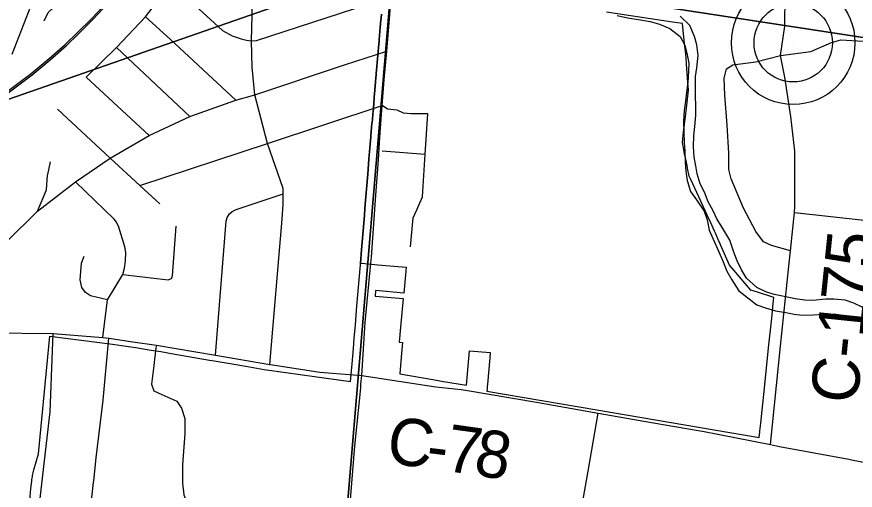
# Model space of a CAD drawing. Extents: x 0 to 34, y 0 to 22.
# Drawn here: x 7.262 to 8.273, y 14.564 to 15.134 of the extents above; entities that cross this region are included whole.
import ezdxf

# ---------------------------------------------------------------- set-up
doc = ezdxf.new("R2010")
doc.units = 0
for name, color, linetype in [('GM_X_City_Street', 7, 'Continuous'), ('GM_X_County_Road', 7, 'Continuous'), ('GM_X_County_Road_Text', 7, 'Continuous'), ('GM_X_Interchange_Ramps', 7, 'Continuous'), ('GM_X_Minor_River', 7, 'Continuous'), ('GM_X_Rail_Line', 7, 'Continuous'), ('GM_X_Section', 7, 'Continuous'), ('GM_X_State_Route', 7, 'Continuous'), ('GM_X_Township_Road', 7, 'Continuous'), ('GM_X_Unincorporated', 7, 'Continuous'), ('GM_X_Unincorporated_Location', 7, 'Continuous')]:
    doc.layers.add(name, color=color, linetype=linetype)

msp = doc.modelspace()

# ---------------------------------------------------------------- linework, layer by layer
at = {"layer": 'GM_X_City_Street'}
for p, q in [((7.471, 15.0143), (7.3826, 15.0975)), ((7.4219, 14.9914), (7.3462, 15.0618)), ((7.7027, 14.973), (7.7546, 14.9688)), ((7.2998, 14.9444), (7.3031, 14.9598))]:
    msp.add_line(p, q, dxfattribs=at)
for points in [[(7.2956, 15.1294), (7.3002, 15.1394), (7.3261, 15.164), (7.3457, 15.1854), (7.3617, 15.2039), (7.4004, 15.2555)], [(7.3462, 15.0618), (7.3826, 15.0975), (7.4175, 15.1342), (7.4486, 15.1748), (7.4783, 15.2152), (7.4829, 15.2225)], [(7.257, 15.0895), (7.2794, 15.1472), (7.2942, 15.1844), (7.2994, 15.1975), (7.304, 15.2071), (7.3103, 15.2134), (7.3166, 15.2172), (7.3232, 15.219), (7.3307, 15.2198), (7.3414, 15.2177), (7.3504, 15.213), (7.3617, 15.2039)], [(7.5673, 14.7157), (7.5821, 14.8909), (7.5835, 14.9088), (7.5833, 14.9212), (7.5835, 14.9278), (7.5646, 14.9819), (7.5493, 15.0405), (7.5461, 15.0737), (7.5451, 15.1054), (7.5461, 15.1362), (7.5462, 15.1432), (7.5449, 15.1482), (7.5428, 15.153), (7.5393, 15.1584), (7.4783, 15.2152)], [(7.4486, 15.1748), (7.5105, 15.118), (7.5219, 15.1115), (7.5328, 15.1077), (7.5392, 15.1061), (7.5451, 15.1054), (7.5512, 15.106), (7.6353, 15.1332), (7.703, 15.1555), (7.7136, 15.1571)], [(7.5263, 15.0338), (7.4473, 15.1074), (7.4175, 15.1342)], [(7.2308, 14.7538), (7.2368, 14.8162), (7.2384, 14.8336), (7.2405, 14.8446), (7.2442, 14.8548), (7.2503, 14.8637), (7.2873, 14.9003), (7.3331, 14.9356), (7.3749, 14.9643), (7.4219, 14.9914), (7.471, 15.0143), (7.5263, 15.0338), (7.5493, 15.0405), (7.6585, 15.0768), (7.7083, 15.093)], [(7.4349, 14.9092), (7.4108, 14.9313), (7.3749, 14.9643), (7.3116, 15.023)], [(7.4108, 14.9313), (7.5646, 14.9819), (7.7026, 15.0274)], [(7.7368, 14.8574), (7.7401, 14.8925), (7.7443, 14.9018), (7.7512, 14.9175), (7.7546, 14.9688), (7.7577, 15.0177), (7.7372, 15.0177), (7.7284, 15.0185), (7.7209, 15.0219), (7.709, 15.0231), (7.7026, 15.0274)], [(7.2873, 14.9003), (7.2981, 14.9259), (7.2996, 14.9436), (7.2998, 14.9444)], [(7.3663, 14.7482), (7.3718, 14.7936), (7.3903, 14.8242), (7.3922, 14.8319), (7.3935, 14.8406), (7.394, 14.8504), (7.3926, 14.8575), (7.3853, 14.8809), (7.3825, 14.8871), (7.3796, 14.8909), (7.3331, 14.9356)], [(7.502, 14.7268), (7.5148, 14.8882), (7.5159, 14.8926), (7.5188, 14.8971), (7.5218, 14.8999), (7.5266, 14.9024), (7.5833, 14.9212)], [(7.3903, 14.8242), (7.445, 14.8178), (7.4487, 14.8191), (7.4501, 14.8223), (7.4543, 14.8823)], [(7.3718, 14.7936), (7.3513, 14.7985), (7.3453, 14.8025), (7.3409, 14.8086), (7.339, 14.8178), (7.3406, 14.8379), (7.3437, 14.8462)]]:
    msp.add_lwpolyline(points, dxfattribs=at)
at = {"layer": 'GM_X_County_Road'}
for points in [[(8.1877, 15.1272), (8.1887, 15.1871), (8.2024, 15.3308), (8.2098, 15.4173), (8.2113, 15.4423), (8.2148, 15.4988), (8.2179, 15.535), (8.2222, 15.5804), (8.2252, 15.5888), (8.2292, 15.5951), (8.2345, 15.6051), (8.2395, 15.6174), (8.2399, 15.6193)], [(8.1703, 14.6193), (8.1826, 14.7378), (8.1925, 14.8342), (8.1944, 14.8527), (8.1992, 14.8986), (8.1999, 14.9058), (8.1999, 14.9725), (8.195, 15.0145), (8.1876, 15.0615), (8.1826, 15.0878), (8.1876, 15.1232), (8.1877, 15.1242), (8.1877, 15.1272)], [(6.8329, 14.8498), (6.8482, 14.844), (6.9195, 14.8112), (6.9871, 14.7803), (7.0307, 14.7606), (7.0448, 14.7578), (7.0584, 14.7574), (7.0804, 14.7567), (7.1007, 14.7554), (7.2308, 14.7538), (7.3064, 14.7532), (7.3663, 14.7482), (7.3733, 14.7474), (7.4023, 14.7431), (7.4307, 14.739), (7.502, 14.7268), (7.5673, 14.7157), (7.5683, 14.7156)], [(7.5683, 14.7156), (7.6276, 14.7067), (7.6681, 14.7032)], [(7.6681, 14.7032), (7.678, 14.7024), (7.7674, 14.6887), (7.7977, 14.6856), (7.8056, 14.6843)], [(7.8056, 14.6843), (7.8884, 14.6702), (7.963, 14.6572), (8.027, 14.6461), (8.0857, 14.636), (8.0885, 14.6354), (8.1703, 14.6193)], [(8.1703, 14.6193), (8.1814, 14.6172), (8.265, 14.6016)], [(8.265, 14.6016), (8.2702, 14.6006), (8.3102, 14.5931), (8.328, 14.59), (8.3817, 14.5804), (8.3909, 14.5788)]]:
    msp.add_lwpolyline(points, dxfattribs=at)
at = {"layer": 'GM_X_Interchange_Ramps'}
for points in [[(7.2768, 14.5377), (7.2796, 14.5666), (7.2802, 14.5724), (7.2805, 14.5754), (7.2807, 14.5771), (7.281, 14.5788), (7.2813, 14.5804), (7.2816, 14.5821), (7.282, 14.5838), (7.2824, 14.5855), (7.2828, 14.5872), (7.2832, 14.5888), (7.2885, 14.6083), (7.2998, 14.7248), (7.3022, 14.7498), (7.3778, 14.7402), (7.3942, 14.738), (7.4082, 14.7359), (7.4104, 14.7355), (7.4219, 14.7336), (7.4242, 14.7332), (7.4359, 14.7312), (7.4508, 14.7286), (7.4947, 14.7211), (7.4977, 14.7206), (7.5196, 14.7168), (7.5383, 14.7136), (7.5603, 14.7099), (7.6646, 14.6952), (7.6664, 14.7164), (7.668, 14.7349), (7.6691, 14.7475), (7.6704, 14.7631), (7.6719, 14.7813), (7.6734, 14.7995), (7.6749, 14.8177), (7.6764, 14.8358), (7.6765, 14.8377), (7.6778, 14.854), (7.6793, 14.8722), (7.6808, 14.8904), (7.6823, 14.9086), (7.6837, 14.9268), (7.6852, 14.945), (7.6867, 14.9631), (7.6889, 14.99), (7.6889, 14.9909), (7.6904, 15.0063), (7.6905, 15.0068), (7.6914, 15.0165), (7.6916, 15.0188), (7.6917, 15.0197), (7.6925, 15.03), (7.6931, 15.0366), (7.6932, 15.0375), (7.6939, 15.046), (7.694, 15.047), (7.6947, 15.0555), (7.6948, 15.0565), (7.6955, 15.0649), (7.6956, 15.0661), (7.6963, 15.0746), (7.6967, 15.0792), (7.6986, 15.1014), (7.6989, 15.105), (7.6992, 15.1091), (7.6993, 15.1099), (7.7, 15.1185), (7.7001, 15.1195), (7.7008, 15.1279), (7.7009, 15.129), (7.7017, 15.1374)], [(7.7017, 15.1374), (7.7009, 15.129), (7.7008, 15.1279), (7.7001, 15.1195), (7.7, 15.1185), (7.6993, 15.1099), (7.6992, 15.1091), (7.6989, 15.105), (7.6986, 15.1014), (7.6967, 15.0792), (7.6963, 15.0746), (7.6956, 15.0661), (7.6955, 15.0649), (7.6948, 15.0565), (7.6947, 15.0555), (7.694, 15.047), (7.6939, 15.046), (7.6932, 15.0375), (7.6931, 15.0366), (7.6925, 15.03), (7.6917, 15.0197), (7.6916, 15.0188), (7.6914, 15.0165), (7.6905, 15.0068), (7.6904, 15.0063), (7.6889, 14.9909), (7.6889, 14.99), (7.6867, 14.9632), (7.6867, 14.9631), (7.6852, 14.945), (7.6837, 14.9268), (7.6823, 14.9086), (7.6808, 14.8904), (7.6793, 14.8722), (7.6778, 14.854), (7.6765, 14.8377), (7.6777, 14.8376), (7.6862, 14.8368), (7.6976, 14.8359), (7.7168, 14.8342), (7.7315, 14.8329), (7.7311, 14.828), (7.7288, 14.8017), (7.6948, 14.8047), (7.6943, 14.7981), (7.7278, 14.7952), (7.7248, 14.7608), (7.7233, 14.7428), (7.7273, 14.7421), (7.7257, 14.7244), (7.724, 14.7044), (7.7635, 14.6977), (7.7766, 14.6954), (7.8042, 14.6907), (7.8078, 14.7323), (7.8328, 14.7301), (7.8323, 14.724), (7.8322, 14.7236), (7.8295, 14.6922), (7.8292, 14.6894), (7.829, 14.6865), (7.8287, 14.6836), (7.9611, 14.6611), (8.1569, 14.6277), (8.1577, 14.6348), (8.1577, 14.6349), (8.1577, 14.6351), (8.1577, 14.6352), (8.1577, 14.6354), (8.1577, 14.6356), (8.1587, 14.6451), (8.1604, 14.6608), (8.1631, 14.6872), (8.1682, 14.7359), (8.1719, 14.7716), (8.1738, 14.7892), (8.1742, 14.793), (8.1745, 14.7962), (8.1745, 14.7966), (8.1549, 14.8027), (8.1468, 14.8053), (8.1262, 14.8294), (8.1262, 14.8295), (8.1212, 14.8354), (8.1102, 14.86), (8.1093, 14.8622), (8.1087, 14.8636), (8.1041, 14.8739), (8.1041, 14.8739), (8.103, 14.8762), (8.0985, 14.8864), (8.0943, 14.8955), (8.084, 14.9177), (8.0743, 14.9385), (8.0724, 14.9425), (8.0705, 14.9523), (8.0699, 14.9552), (8.0699, 14.9553), (8.0687, 14.9611), (8.067, 14.9695), (8.0656, 14.9768), (8.0644, 14.983), (8.0653, 14.9916), (8.0662, 14.9987), (8.0665, 15.0019), (8.0672, 15.0079), (8.0687, 15.0207), (8.0716, 15.0461), (8.0716, 15.0473), (8.0714, 15.05), (8.0694, 15.0774), (8.0688, 15.0852), (8.0679, 15.0928), (8.067, 15.1019), (8.0664, 15.1067), (8.0653, 15.1173), (8.0652, 15.1181), (8.0648, 15.1218), (8.0643, 15.1262), (8.0615, 15.1266), (8.0525, 15.128), (7.9728, 15.1401)]]:
    msp.add_lwpolyline(points, dxfattribs=at)
at = {"layer": 'GM_X_Minor_River'}
for points in [[(7.9857, 15.136), (7.9982, 15.1331), (8.0114, 15.1313), (8.0254, 15.1287), (8.0367, 15.1255), (8.0492, 15.1203), (8.0615, 15.1105), (8.0674, 15.1001), (8.0702, 15.0887), (8.0719, 15.0784), (8.0717, 15.0688), (8.0707, 15.0552), (8.0693, 15.0438), (8.0679, 15.0328), (8.0666, 15.0214), (8.0656, 15.0081), (8.0661, 14.9955), (8.0666, 14.9826), (8.0672, 14.973), (8.0676, 14.9593), (8.0686, 14.9487), (8.0702, 14.9372), (8.0742, 14.9242), (8.0812, 14.9142), (8.0904, 14.9003), (8.094, 14.8899), (8.0964, 14.8773), (8.1015, 14.8666), (8.1084, 14.8512), (8.1135, 14.8393), (8.1178, 14.8282), (8.1237, 14.8178), (8.1325, 14.8044), (8.143, 14.7962), (8.1542, 14.7876), (8.1644, 14.784), (8.1764, 14.7803), (8.1889, 14.7785)], [(8.187, 14.7976), (8.1749, 14.8001), (8.1648, 14.8033), (8.1542, 14.8085), (8.1416, 14.8198), (8.1357, 14.8298), (8.1302, 14.8405), (8.1262, 14.8509), (8.1216, 14.8654), (8.1131, 14.8793), (8.1058, 14.8912), (8.1014, 14.9008), (8.0955, 14.9116), (8.0908, 14.9231), (8.0857, 14.9331), (8.0822, 14.9453), (8.0805, 14.9549), (8.0784, 14.9652), (8.0779, 14.9782), (8.0781, 14.9911), (8.0796, 15.0063), (8.0805, 15.0165), (8.0807, 15.0261), (8.0802, 15.0401), (8.0801, 15.0508), (8.0803, 15.0626), (8.0816, 15.0728), (8.0834, 15.0876), (8.0818, 15.1006), (8.0789, 15.1106), (8.0731, 15.124), (8.0616, 15.1353)], [(8.2809, 14.7847), (8.2707, 14.7895), (8.2605, 14.7931), (8.2469, 14.7945), (8.237, 14.7943), (8.2215, 14.7927), (8.212, 14.7933), (8.2002, 14.7947), (8.187, 14.7976)], [(8.1889, 14.7785), (8.1991, 14.7764), (8.209, 14.7751), (8.2223, 14.7756), (8.2337, 14.7765), (8.2469, 14.7766), (8.2606, 14.7749), (8.2745, 14.7723)]]:
    msp.add_lwpolyline(points, dxfattribs=at)
at = {"layer": 'GM_X_Rail_Line'}
for points in [[(7.2404, 15.037), (7.2637, 15.0539), (7.2798, 15.0661), (7.3016, 15.084), (7.3209, 15.1012), (7.3352, 15.115), (7.3528, 15.1324), (7.3648, 15.1452)], [(7.2415, 15.0354), (7.2648, 15.0523), (7.281, 15.0646), (7.3028, 15.0825), (7.3222, 15.0998), (7.3365, 15.1136), (7.3541, 15.1311), (7.3662, 15.1439)]]:
    msp.add_lwpolyline(points, dxfattribs=at)
at = {"layer": 'GM_X_Section'}
for points in [[(7.0978, 16.2238), (7.8045, 16.1663), (7.7155, 15.1965), (6.679, 14.8357), (6.7178, 15.1451), (6.8557, 15.1486), (6.9495, 15.1616), (7.0625, 15.1905), (7.1067, 15.2265), (7.1794, 15.3058), (7.2286, 15.3847), (7.2695, 15.5468), (7.2556, 15.6944), (7.2482, 15.743), (7.2442, 15.8333), (7.2274, 15.9468)], [(7.8045, 16.1663), (8.8322, 16.077), (8.7359, 15.0399), (7.7155, 15.1965)], [(7.7155, 15.1965), (8.7359, 15.0399), (8.6553, 14.0079), (7.6347, 14.2379)]]:
    msp.add_lwpolyline(points, close=True, dxfattribs=at)
msp.add_lwpolyline([(6.6081, 14.0019), (6.679, 14.8357), (7.7155, 15.1965), (7.6347, 14.2379), (7.0538, 14.0019)], dxfattribs=at)
at = {"layer": 'GM_X_State_Route'}
for points in [[(7.6981, 14.9622), (7.6999, 14.9895), (7.7026, 15.0274), (7.705, 15.0585), (7.7083, 15.093), (7.7136, 15.1571), (7.7158, 15.1775), (7.7161, 15.1815)], [(7.6895, 14.8419), (7.6898, 14.845), (7.6952, 14.9198), (7.6981, 14.9622)], [(7.6771, 14.6919), (7.678, 14.7024), (7.6823, 14.7664), (7.6891, 14.8379), (7.6895, 14.8419)], [(7.6593, 14.4904), (7.6625, 14.5284), (7.6699, 14.6176), (7.6768, 14.6878), (7.6771, 14.6919)]]:
    msp.add_lwpolyline(points, dxfattribs=at)
at = {"layer": 'GM_X_Township_Road'}
msp.add_line((7.306, 14.743), (7.3064, 14.7532), dxfattribs=at)
for points in [[(8.1826, 15.0878), (8.219, 15.0927), (8.2438, 15.1034), (8.2554, 15.1068), (8.336, 15.1019), (8.3554, 15.1005), (8.3695, 15.0951), (8.3758, 15.083), (8.3753, 15.0694), (8.3748, 15.0524), (8.3763, 15.0262), (8.4204, 15.0204), (8.4438, 15.0203)], [(8.1944, 14.8527), (8.1716, 14.859), (8.1622, 14.8636), (8.1529, 14.8758), (8.138, 14.9038), (8.1231, 14.9393), (8.1203, 14.9504), (8.1203, 14.97), (8.1184, 15.0037), (8.1156, 15.0401), (8.1147, 15.0606), (8.1175, 15.0718), (8.1249, 15.0765), (8.1529, 15.0802), (8.1826, 15.0878)], [(8.1992, 14.8986), (8.327, 14.8849), (8.3293, 14.8849), (8.3314, 14.885), (8.3342, 14.8852), (8.345, 14.8887), (8.3624, 14.8951), (8.3649, 14.8965), (8.3682, 14.8987), (8.3705, 14.9009), (8.3728, 14.9034)], [(7.3552, 14.5757), (7.3581, 14.6033), (7.3665, 14.6728), (7.3733, 14.7474)], [(7.289, 14.5407), (7.3026, 14.6589), (7.306, 14.743)], [(7.4307, 14.739), (7.43, 14.7358), (7.4276, 14.7145), (7.4248, 14.6922), (7.4276, 14.6839), (7.4373, 14.6797), (7.4554, 14.6714), (7.4609, 14.6631), (7.4651, 14.6506), (7.4651, 14.6325), (7.4623, 14.595), (7.4623, 14.5728), (7.4637, 14.5589), (7.4693, 14.545), (7.479, 14.5297), (7.4956, 14.5089)], [(7.9134, 14.378), (7.9256, 14.4478), (7.9331, 14.4891), (7.9387, 14.5196), (7.9508, 14.5873), (7.963, 14.6572)], [(7.6467, 14.3474), (7.5863, 14.3552), (7.579, 14.3561), (7.4845, 14.3658), (7.4595, 14.3714), (7.4331, 14.3811), (7.4109, 14.3936), (7.3887, 14.4109), (7.3776, 14.4269), (7.3665, 14.4464), (7.3568, 14.4658), (7.352, 14.4812), (7.3512, 14.4839), (7.3498, 14.5047), (7.3498, 14.5255), (7.3506, 14.5334), (7.3526, 14.5519), (7.3549, 14.5737), (7.3552, 14.5757)]]:
    msp.add_lwpolyline(points, dxfattribs=at)
at = {"layer": 'GM_X_Unincorporated'}
for radius in [0.0744, 0.0472]:
    msp.add_circle((8.1978, 15.1031), radius, dxfattribs=at)
at = {"layer": 'GM_X_Unincorporated_Location'}
msp.add_line((8.1978, 15.1031), (8.1978, 15.1031), dxfattribs=at)

# ---------------------------------------------------------------- texts
at = {"layer": 'GM_X_County_Road_Text'}
for s, height, rotation, p in [('C-175', 0.05682, 84.0948, (8.2749, 14.6673)), ('C', 0.0568, 350.9823, (7.7058, 14.5983)), ('7', 0.0568, 351.9862, (7.777, 14.5879)), ('8', 0.0568, 350.7387, (7.8114, 14.5831)), ('-', 0.0568, 353.0877, (7.7542, 14.5907))]:
    msp.add_text(s, height=height, rotation=rotation, dxfattribs=at).set_placement(p)

doc.saveas('drawing.dxf')
